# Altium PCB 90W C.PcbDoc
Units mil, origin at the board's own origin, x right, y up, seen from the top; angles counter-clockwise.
Board outline 3425 x 3275 mil, 2 copper layers (Top Layer, Bottom Layer); 75 components, 57 nets, 187 pads, 17 vias.
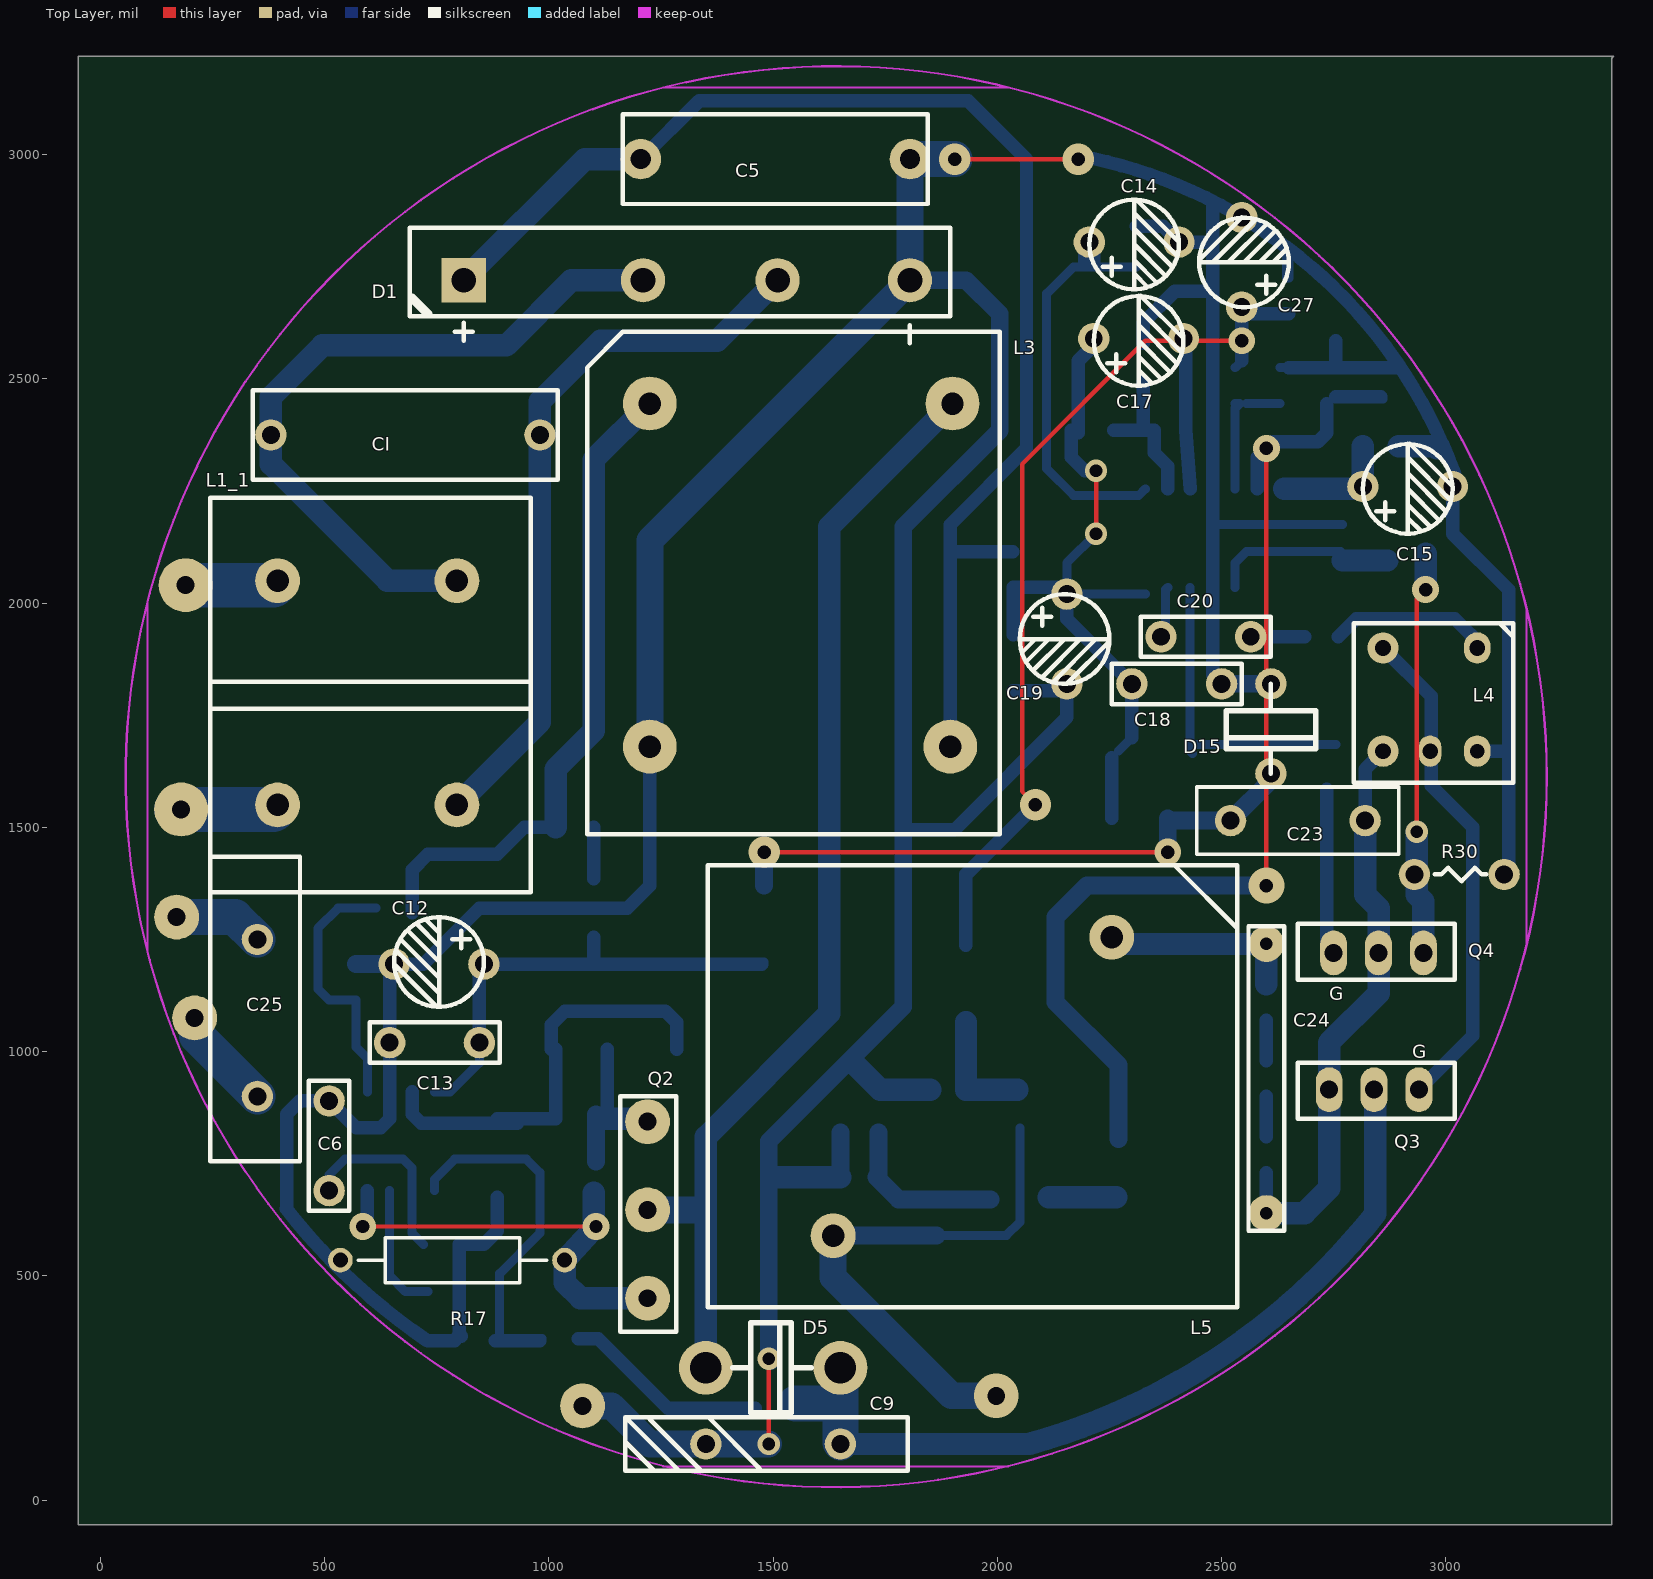
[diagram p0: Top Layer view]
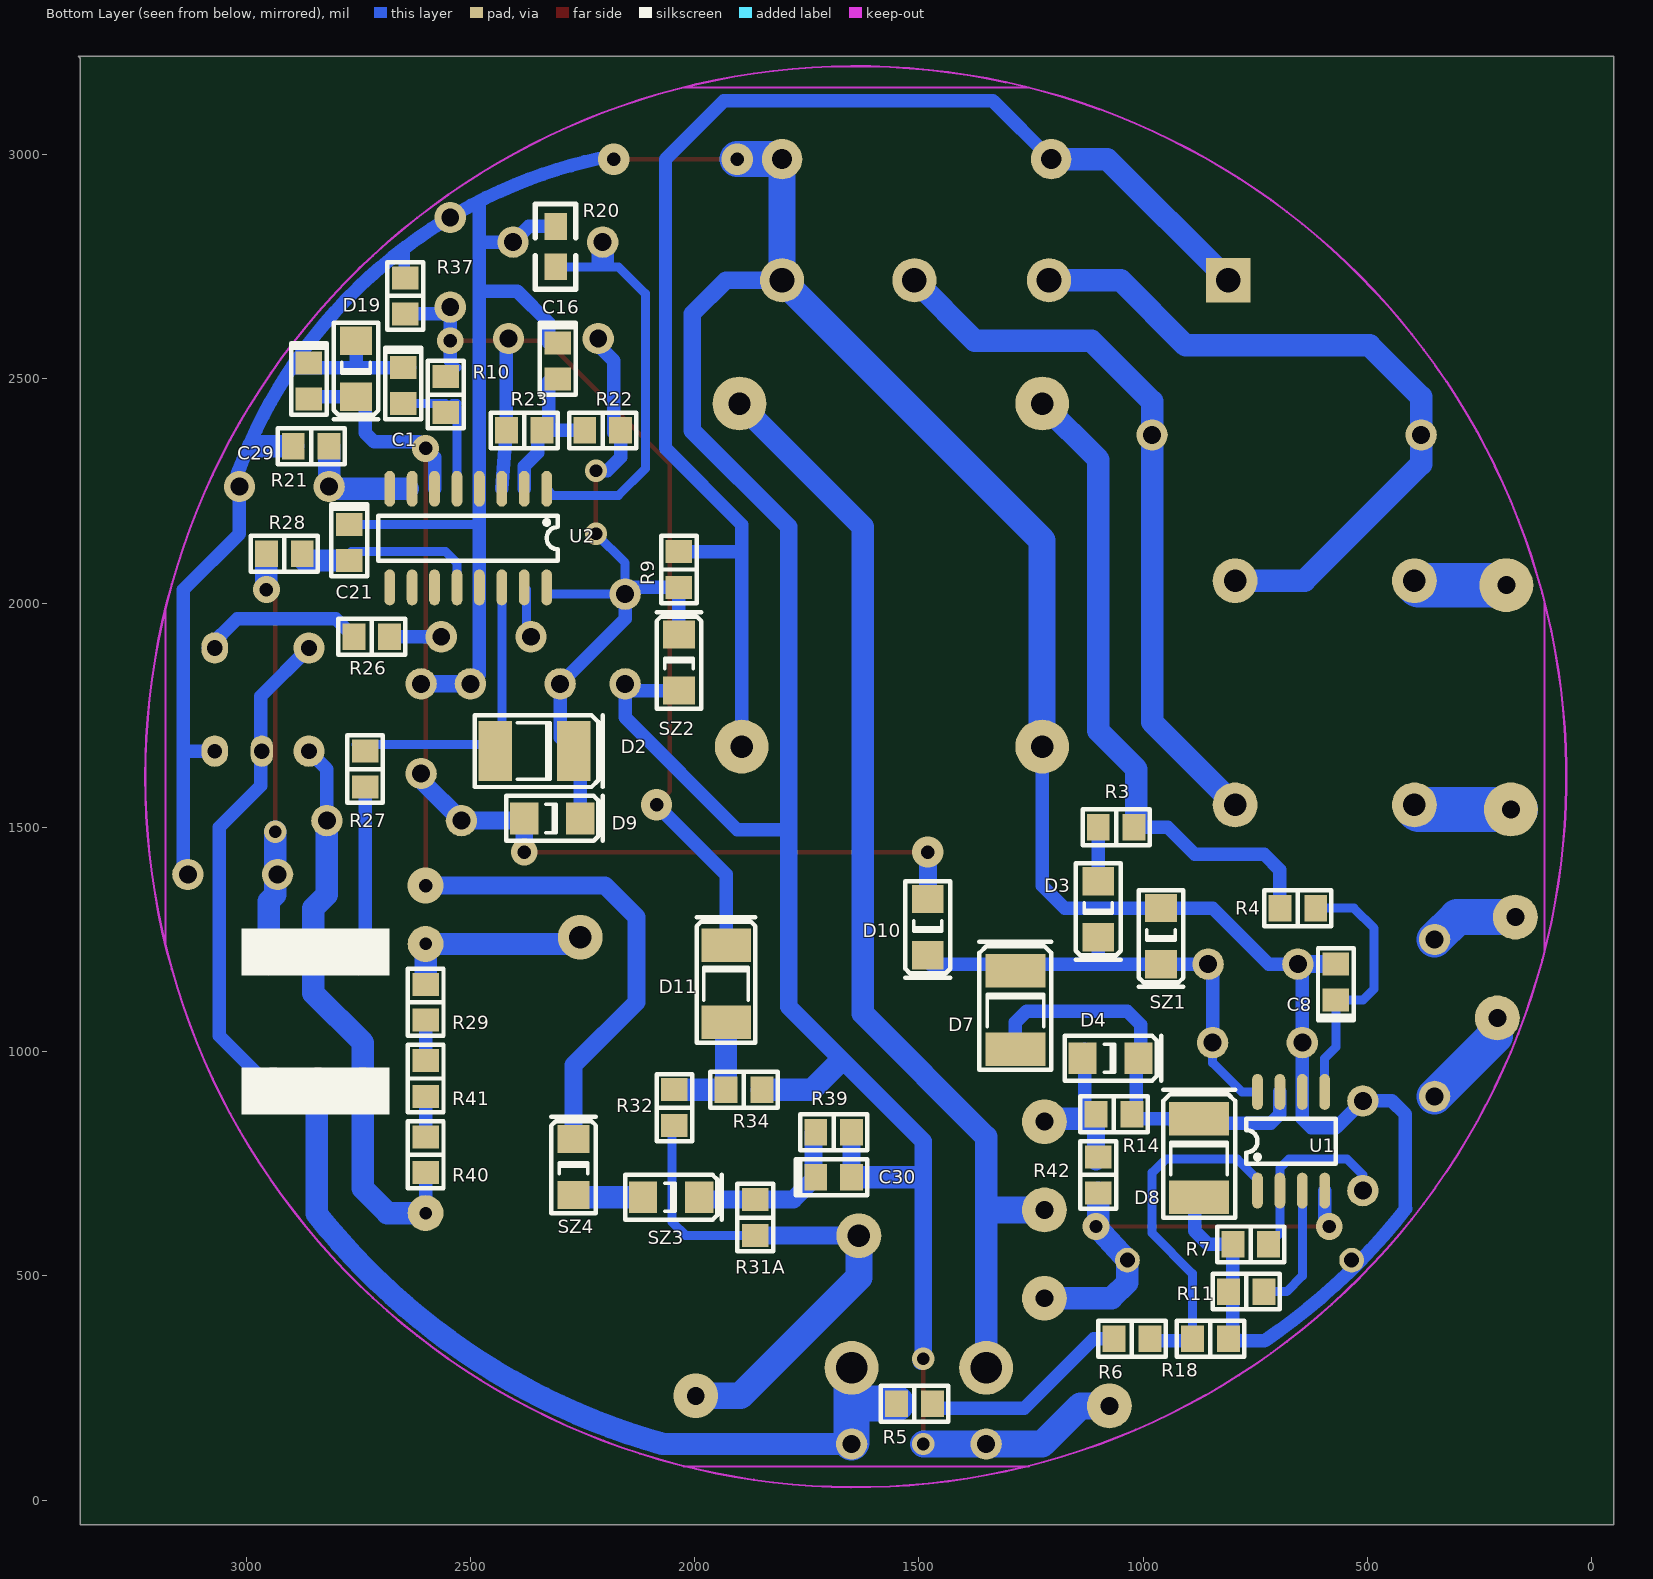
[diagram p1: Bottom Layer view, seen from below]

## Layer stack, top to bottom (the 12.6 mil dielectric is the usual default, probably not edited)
Top Layer: signal copper 1.4
Dielectric: dielectric 12.6, FR-4, Dk 4.8
Bottom Layer: signal copper 1.4

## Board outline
1685,3220 -50,3220 -50,-55 3370,-55 3370,3215 3375,3220

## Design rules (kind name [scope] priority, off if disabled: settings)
Clearance [All] p1: gap=10
HoleSize [All] p1: absolutevalues=TRUE maxlimit=150 minlimit=1 maxpercent=80.000 minpercent=20.000
PlaneClearance [All] p1: clearance=10
PolygonConnect [All] p1: connectstyle=Direct reliefconductorwidth=10 reliefentries=4 polygonreliefangle="90 Angle"
RoutingVias [All] p1: holewidth=28 width=50 viastyle="Through Hole" minholewidth=28 minwidth=50 maxholewidth=28 maxwidth=50
SolderMaskExpansion [All] p1: expansion=4
TestPointUsage [All] p1: valid=0 allowmultiple=FALSE
Testpoint [All] p1: side=15 testpointundercomponent=TRUE minsize=40 maxsize=100 preferedsize=60 minholesize=0 maxholesize=40 preferedholesize=32 testpointgrid=1 style=1023 order=0-112345678
Width [All] p1: maxlimit=100 minlimit=10 preferedwidth=10 toplayer_maxwidth=10 bottomlayer_minwidth=20 bottomlayer_prefwidth=40 minimp=50.000000 maximp=50.000000 favimp=50.000000
17 further rules are at their usual default settings.

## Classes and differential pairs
net class NewClass: GND

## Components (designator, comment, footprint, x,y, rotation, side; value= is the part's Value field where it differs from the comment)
C1 "Comment" C0805A 2650,2485 r270 bottom
C5 "CAP" RAD0.6B#1 1805,2990 r180 top
C6 "CAP" RAD0.2B 510,890 r270 top
C8 "CAP" C0805A 570,1155 r90 bottom
C9 "Cap2" RB.3/.6C 1650,125 r270 top
C12 "CAP" RB.2/.2 755,1195 r270 top
C13 "Comment" RAD0.2B 845,1020 r180 top
C14 "Cap" RB.2/.2 2305,2805 r90 top
C15 "Cap" RB.2/.2 2915,2260 r90 top
C16 "Cap" C0805A 2305,2540 r270 bottom
C17 "Cap2" RB.2/.2 2315,2590 r90 top
C18 "CAP" RAD0.2B 2500,1820 r180 top
C19 "Cap" RB.2/.2 2155,1920 r0 top
C20 "CAP" RAD0.2B 2565,1925 r180 top
C21 "CAP" C0805A 2770,2135 r270 bottom
C23 "CAP" RAD-0.3 2670,1515 r180 top
C24 "CAP" CAD0.6 2600,1240 r270 top
C25 "Comment" RAD0.6A 450,750 r90 top
C27 "Cap2" RB.2/.2 2545,2760 r180 top
C29 "Cap" C0805A 2860,2495 r270 bottom
C30 "Cap" C0805A 1690,720 r180 bottom
CI "" RAD0.6B#2 340,2275 r0 top
D1 "DIODEx4" HY_GBJ_606 810,2720 r90 top
D2 "Comment" CD4532-1812A 2350,1670 r180 bottom
D3 "DIODE" CD3216-1206A 1100,1320 r270 bottom
D4 "DIODE" CD3216-1206A 1075,985 r180 bottom
D5 "HIGH EFFICIENCY DIODES" DIODE0.7B 1350,295 r0 top
D7 "Comment" CD4532-1812A 1285,1100 r90 bottom
D8 "Comment" CD4532-1812A 875,770 r90 bottom
D9 "DIODE" CD3216-1206A 2320,1520 r180 bottom
D10 "DIODE" CD3216-1206A 1480,1280 r270 bottom
D11 "DIODE" CD4532-1810 1930,1160 r90 bottom
D15 "FFAST RECOVERY RECTIFIER" DIODE0.2A 2610,1820 r270 top
D19 "DIODE" CD3216-1206A 2755,2525 r270 bottom
L1_1 "Comment" EE2225_EMI 395,1550 r0 top
L3 "Comment" ER28 1090,2610 r270 top
L4 "INDUCTOR2:2" EE0808 2965,1670 r180 top
L5 "INDUCTOR2A" EI3028 2535,1415 r180 top
Q2 "K2628" MOS 1220,450 r90 top
Q3 "MOSFET-N" TO-220D 2840,915 r180 top
Q4 "MOSFET-N" TO-220D 2850,1220 r0 top
R3 "RES1" 2012[0805]A 1060,1500 r0 bottom
R4 "RES1" 2012[0805]A 655,1320 r180 bottom
R5 "RES1" 2012[0805]A 1510,215 r0 bottom
R6 "RES1" 2012[0805]A 1025,360 r180 bottom
R7 "Res1" 2012[0805]A 760,570 r180 bottom
R9 "RES1" 2012[0805]A 2035,2075 r90 bottom
R10 "RES1" 2012[0805]A 2555,2465 r270 bottom
R11 "RES1" 2012[0805]A 770,465 r0 bottom
R14 "RES1" 2012[0805]A 1065,860 r0 bottom
R17 "RES1" AXIAL-0.5 785,535 r0 top
R18 "RES1" 2012[0805]A 850,360 r0 bottom
R20 "RES1" 0805 2310,2840 r270 bottom
R21 "RES1" 2012[0805]A 2855,2350 r180 bottom
R22 "RES1" 2012[0805]A 2205,2385 r180 bottom
R23 "RES1" 2012[0805]A 2380,2385 r0 bottom
R26 "RES1" 2012[0805]A 2720,1925 r180 bottom
R27 "RES1" 2012[0805]A 2735,1630 r270 bottom
R28 "RES1" 2012[0805]A 2915,2110 r180 bottom
R29 "Res1" 2012[0805]A 2600,1110 r270 bottom
R30 "RES1" Axial0.2 3130,1395 r180 top
R31A "RES1" 2012[0805]A 1865,630 r270 bottom (schematic designator R31)
R32 "RES1" 2012[0805]A 2045,875 r90 bottom
R34 "RES1" 2012[0805]A 1890,915 r0 bottom
R37 "RES1" 2012[0805]A 2645,2685 r270 bottom
R39 "RES1" 2012[0805]A 1690,820 r0 bottom
R40 "Res1" 2012[0805]A 2600,770 r90 bottom
R41 "Res1" 2012[0805]A 2600,940 r270 bottom
R42 "RES1" 2012[0805]A 1100,725 r270 bottom
SZ1 "Zener" CD3216-1206A 960,1260 r270 bottom
SZ2 "Zener" CD3216-1206A 2035,1865 r90 bottom
SZ3 "Zener" CD3216-1206A 2055,675 r180 bottom
SZ4 "Zener" CD3216-1206A 2270,740 r90 bottom
U1 "IC" SO-8 745,690 r90 bottom
U2 "IC" "SO-16 A" 2330,2255 r270 bottom

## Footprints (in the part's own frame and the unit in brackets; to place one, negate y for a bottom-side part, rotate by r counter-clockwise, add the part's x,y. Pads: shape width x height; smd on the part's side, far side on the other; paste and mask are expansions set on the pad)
0805 [mil]
  rect 60x50 smd: 1(0,0) 2(90,0)
  silkscreen extent -50,-45 140,45
2012[0805]A [mm] "Chip Resistor; Body 2.0 x 1.3 mm (LxW typ)"
  rect 1.3x1.5 smd: 1(-1.016,0) 2(1.016,0)
  silkscreen extent -1.91,-1.02 1.91,1.02
Axial0.2 [mil]
  round 70 hole 40: 1(0,0) 2(200,0)
  silkscreen extent 40,-15 155,15
AXIAL-0.5 [mm] "Semiconductor Resistor; 2 Leads"
  round 1.4 hole 0.85: 1(-6.35,0) 2(6.35,0)
  silkscreen extent -5.33,-1.27 5.33,1.27
C0805A [mm] "Chip Capacitor; Body 2.0 x 1.2 mm (LxW typ)"
  rect 1.3x1.5 smd: 1(-1.016,0) 2(1.016,0)
  silkscreen extent -2.16,-1.02 1.91,1.02
CAD0.6 [mil]
  round 80 hole 28: 1(0,0) 2(600,0)
  silkscreen extent -40,-40 640,40
CD3216-1206A [mm] "Chip Diode; Body 3.2 x 1.6 mm (LxW typ)"
  rect 1.6x1.8 smd: 1(-1.524,0) 2(1.651,0)
  silkscreen extent -2.54,-1.27 2.92,1.27
CD4532-1810 [mm] "Chip Diode; Body 4.5 x 3.2 mm (LxW typ)"
  rect 1.9x2.8 smd: 1(-2.413,0) 2(1.95,0)
  silkscreen extent -3.56,-1.65 3.56,1.65
CD4532-1812A [mm] "Chip Diode; Body 4.5 x 3.2 mm (LxW typ)"
  rect 1.9x3.4 smd: 1(-2.413,0) 2(2.032,0)
  silkscreen extent -3.56,-2.03 3.68,2.03
DIODE0.2A [mil] "Tunnel Diode - Dependent Source Model; 2 Leads"
  round 70 hole 40: 1(0,0) 2(200,0)
  silkscreen extent 0,-100 200,100
DIODE0.7B [mil]
  round 120 hole 70: 1(0,0) 2(300,0)
  silkscreen extent 60,-100 235,100
EE0808 [mil]
  oval 59.06x70 hole 35: 1(-105,-230)
  round 70 hole 35: 3(105,-230) 4(105,0)
  oval 50x70 hole 35: 5(0,0)
  oval 59.06x70 hole 32: 6(-105,0)
  silkscreen extent -185,-285 170,70
EE2225_EMI [mil]
  round 100 hole 50: 1(0,0) 2(400,0) 3(400,500) 4(0,500)
  silkscreen extent -150,-195 565,685
EI3028 [mil]
  round 100 hole 50: 1(280,160) 5(901.1,825.51)
  silkscreen extent 0,0 1181,986
ER28 [mil]
  round 120 hole 50: 1(165,135) 5(930,135) 6(930,805) 10(165,810)
  silkscreen extent 5,-5 1125,915
HY_GBJ_606 [mm]
  rect 2.5x2.5 hole 1.4: 1(0,0)
  round 2.5 hole 1.4: 2(0,-10.16) 3(0,-17.78) 4(0,-25.273)
  silkscreen extent -3.56,-27.56 2.97,3.05
MOS [mil]
  round 100 hole 40: 1(0,0) 2(196.85,0) 3(393.7,0)
  silkscreen extent -75,-64 450,61
RAD0.2B [mil]
  round 70 hole 40: 1(0,0) 2(200,0)
  silkscreen extent -45,-45 245,45
RAD0.6A [mil]
  round 70 hole 40: 1(150,100) 2(500,100)
  silkscreen extent 5,5 685,205
RAD0.6B#1 [mil]
  round 90 hole 45: 1(0,0) 2(600,0)
  silkscreen extent -40,-100 640,100
RAD0.6B#2 [mil]
  round 70 hole 40: 1(40,100) 2(640,100)
  silkscreen extent 0,0 680,200
RAD-0.3 [mil] "Capacitor; 2 Leads"
  round 70 hole 40: 1(-150,0) 2(150,0)
  silkscreen extent -225,-75 225,75
RB.2/.2 [mil]
  round 70 hole 40: 1(0,100) 2(0,-100)
  silkscreen extent -105,-100 95,100
RB.3/.6C [mil]
  round 70 hole 40: 1(0,0) 2(0,-300)
  silkscreen extent -60,-480 60,150
SO-8 [mil]
  oval 80x24 smd: 1(0,0) 2(0,-50) 3(0,-100) 4(0,-150) 5(220,-150) 6(220,-100) 7(220,-50) 8(220,0)
  silkscreen extent 60,-175 160,25
"SO-16 A" [mil]
  oval 80x24 smd: 0(0,-350) 0(220,-350) 1(0,0) 2(0,-50) 3(0,-100) 4(0,-150) 5(0,-200) 6(0,-250) 7(0,-300) 8(220,-300) 9(220,-250) 10(220,-200) 11(220,-150) 12(220,-100) 13(220,-50) 14(220,0)
  silkscreen extent 60,-375 160,25
TO-220D [mil]
  oval 60x100 hole 40: 1(0,0) 2(-100,0) 3(100,0)
  silkscreen extent -180,-60 170,65

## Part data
C5 C23 C24: "POLYPROPYLENE FILM Capacitor"
C6 C8 C16 C18 C20 C21 C29 C30: "Ceramic Capacitor"
C9 C17 C27: "Electrolytic Capacitor"
C12 C14 C15 C19: library part Cap2, "Electrolytic Capacitor"
D3 D4 D9 D10 D11 D19: "Diode  75V,1A"
D5: library part DIODE, "Diode HIGH EFFICIENCY RECTIFIERS 600V, 3A"
D15: library part DIODE, "Diode FAST RECOVERY RECTIFIER 700V,1A"
L4: "EE08 Inductor"
L5: "EE25 Inductor"
Q3 Q4: "Transistor, MOSFET  600V, 6A"
R3 R4 R5 R6 R9 R10 R11 R14 R18 R20 R21 R22 R23 R26 R27 R28 R29 R31A R32 R34 R37 R39 R40 R41 R42: "Resistor 1/4W"
R7: "Resistor"
R17 R30: "Resistor 1W"
SZ1 SZ2: library part "D Zener", "Zener Diode 1W"
SZ3 SZ4: library part "D Zener", "Zener Diode 1/4W"
U1: library part 59039, "IC, Power Factor Controller"
U2: library part M8145, "IC, Ballast Driver"

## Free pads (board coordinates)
  round 100 hole 40: 0(170,1300) 0(1075,210) 1(210,1075)
  round 120 hole 40: 0(190,2040) 1(180,1540)

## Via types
v1: diameter 60, hole 30, Top Layer to Bottom Layer, 6 vias
v2: diameter 50, hole 28, Top Layer to Bottom Layer, 5 vias
v3: diameter 70, hole 30, Top Layer to Bottom Layer, 4 vias
v4: diameter 100, hole 40, Top Layer to Bottom Layer, 1 vias
v5: diameter 80, hole 30, Top Layer to Bottom Layer, 1 vias

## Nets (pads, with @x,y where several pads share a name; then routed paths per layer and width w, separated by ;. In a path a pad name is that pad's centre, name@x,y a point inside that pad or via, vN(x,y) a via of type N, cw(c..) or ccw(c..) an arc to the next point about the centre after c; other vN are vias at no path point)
GND: C1.1 C5.1 C6.1 C8.2 C9.2 C12.2 C13.2 C14.2 C15.2 C16.1 C18.1 C19.2 C21.1 C27.2 C29.1 C30.2 D1.4 D8.1 D15.1 D19.1 L3.5 L4.6 pad.0@1075,210 R7.1 R11.2 R17.1 R18.1 R20.1 R21.1 R30.1 R34.1 R37.1 R39.1 SZ1.1 SZ2.1 U1.6 U2.4 U2.11 | length 13879.7
  Top Layer w10: v2(1490,125) v2(1490,315) ; v3(1905,2990) v3(2180,2990)
  Bottom Layer w20: 2475,2895 2480,2890 ; 2485,2175 C21.1 ; C27.2@2530,2845 2530,2869.44 C27.2@2530,2875 ; C1.1@2630,2525 C1.1 ; R37.1 2645,2793.52 2645,2795 ; R37.1@2650,2725 2650,2785 ; 2895,2525 2900,2520 ; 2980,2345 2995,2345
  Bottom Layer w30: 414.43,649.56 ccw(c1507.5,1502.5) 727.46,356.27 ; 415,654.8 415,860 445,890 C6.1 570,830 625,830 645,850 U1.6 C13.2 645,1190 C12.2@650,1195 ; C12.2 720,1195 845,1320 SZ1.1 1175,1320 1225,1370 L3.5 L3.5@1225,1640 ; 730,355 790,355 R18.1@800,370 ; R18.1@805,365 R18.1@800,370 ; D8.1@885,675 885,600 855,570 R7.1 R18.1@800,370 ; 1790,1495 1905,1495 2155,1745 C19.2 ; SZ2.1 C19.2@2140,1805 ; v3@2181.48,2997.91 cw(c1977.48,1907.48) 2400,2933.21 cw(c1977.48,1907.48) 2530,2869.44 cw(c1977.48,1907.48) 2645,2793.52 cw(c1977.48,1907.48) C15.2@3030.89,2255.29 ; R20.1 2370,2840 C14.2 2475,2805 2480,2800 ; C16.1@2325,2580 2325,2625 2395,2695 2480,2695 ; 2480,2890 2480,2800 ; C18.1 2480,1840 U2.11 U2.4 2480,2695 ; C1.1 2895,2525 ; 2755,2530 D19.1 ; C15.2 3015,2155 3140,2030 3140,1670 ; L4.6 3140,1670 ; R30.1@3140,1395 3140,1670 ; 2480,2695 2480,2800
  Bottom Layer w39.37: v2@1495,310 v2(1490,315) 1490,800 1790,1100 1790,2170 2005,2385 2005,2645 1930,2720 D1.4 ; C18.1 D15.1
  Bottom Layer w40: C8.2 C12.2@650,1195 ; C30.2 R39.1
  Bottom Layer w50: 1505,720 C30.2 ; 1679.29,974.29 1738.57,915 R34.1 ; R21.1 2975,2350 2980,2345
  Bottom Layer w60: pad.0@1075,210 1140,210 1225,125 C9.2 v2(1490,125) ; L3.5 1225,2140 D1.4 C5.1
  Bottom Layer w80: C5.1 v3(1905,2990)
L: 
N: 
NetC2_2: 
NetC4_1: 
NetC5_2: C5.2 D1.1 L3.6 R9.2 | length 2994.6
  Bottom Layer w30: C5.2 1334.8,3119.8 1935.2,3119.8 2065,2990 2065,2345 1895,2175 1895,2154.8 L3.6 ; 1895,2115 R9.2@2034.8,2115
  Bottom Layer w50: D1.1 1080,2990 C5.2
NetC6_2: C6.2 R7.2 U1.2 | length 423.1
  Bottom Layer w20: C6.2 510,725 545,760 675,760 695,740 U1.2 695,595 R7.2
NetC8_1: C8.1 R4.2 U1.5 | length 594.4
  Bottom Layer w20: U1.5 595,985 570,1010 C8.1 510,1115 485,1140 485,1275 530,1320 R4.2
NetC9_1: C9.1 D5.2 Q3.1 R5.2 | length 1911.4
  Bottom Layer w30: Q3.1 Q3.1@2842.49,912.51
  Bottom Layer w50: C9.1 2070.5,125 ccw(c1670,1565) 2842.49,638.03 ; 2842.49,638.03 Q3.1@2842.49,912.51
  Bottom Layer w60: 1639.8,215 1650,204.8
  Bottom Layer w80: R5.2 1639.8,215 ; C9.1@1650,128.75 1650,204.8 D5.2
NetC11_2: 
NetC12_1: C12.1 C13.1 D3.2 D7.2 D10.2 SZ1.2 U1.8 | length 1038.1
  Bottom Layer w20: U1.8 780,910 845,975 C13.1 ; C12.1@845,1185 C12.1 ; D10.2@1475,1195 D10.2@1480,1200
  Bottom Layer w30: C13.1 C12.1@845,1185 ; C12.1 SZ1.2 1100,1195 ; D3.2 1100,1195 ; D10.2@1475,1195 1100,1195
NetC14_1: C14.1 R20.2 U2.1 | length 913
  Bottom Layer w20: 2205,2755 2200,2750 ; R20.2 2200,2750 ; U2.1 2315,2240 2170,2240 2110,2300 2110,2690 2170,2750 2200,2750
  Bottom Layer w50: 2205,2765 C14.1
NetC15_1: C15.1 R21.2 U2.0@2680,2255 U2.7 | length 270
  Bottom Layer w50: U2.7@2640,2255 2680,2255 2815,2255 R21.2
NetC16_2: C16.2 R22.1 R23.1 U2.2 | length 344.5
  Bottom Layer w30: R22.1@2260,2385 R23.1@2330,2385 ; C16.2@2325,2495 2325,2390 R23.1@2330,2385 ; U2.2 2380,2305 2350,2335 2350,2385 R23.1@2330,2385
NetC17_2: C17.2 R23.2 U2.3 | length 335.4
  Bottom Layer w30: C17.2@2420,2590 R23.2 U2.3
NetC20_1: C20.1 R26.2 | length 120
  Bottom Layer w30: C20.1 R26.2@2685,1925
NetC20_2: C20.2 U2.13 | length 112.1
  Bottom Layer w20: C20.2@2375,1925 2375,2030 U2.13
NetC21_2: C21.2 R28.2 U2.10 | length 407.4
  Bottom Layer w20: U2.10 2530,2090 2555,2115 2765,2115 C21.2@2770,2110
  Bottom Layer w50: C21.2 R28.2@2870,2095
NetC23_1: C23.1 C24.2 L4.4 Q3.3 Q4.1 R40.1 | length 1302.3
  Bottom Layer w30: C24.2 R40.1 ; C23.1 2820,1630 L4.4
  Bottom Layer w50: C24.2 2685,640 2740,695 Q3.3 2740,1020 2850,1130 Q4.1 2850,1320 2820,1350 C23.1
NetC23_2: C23.2 D9.1 D10.1 D15.2 | length 1334.4
  Top Layer w10: v3(1480,1445) v1(2380,1445)
  Bottom Layer w40: D10.1@1480,1370 v3(1480,1445) ; v1(2380,1445) D9.1 2385,1515 C23.2 2610,1605 D15.2
NetC25_1: 
NetC25_2: 
NetC26_1: 
NetC26_2: 
NetC27_1: C27.1 D11.2 R10.1 R37.2 | length 1985
  Top Layer w10: v3(2085,1550) 2055,1580 2055,2310 2330,2585 v1(2545,2585)
  Bottom Layer w20: R10.1@2530,2525 2545,2540
  Bottom Layer w30: D11.2 1930,1395 v3(2085,1550) ; 2545,2540 2545,2645 R37.2@2650,2645
NetC28_1: 
NetC30_1: C30.1 R31A.1 R39.2 SZ3.2 | length 382.8
  Bottom Layer w20: SZ3.2@1985,670 SZ3.2
  Bottom Layer w40: C30.1 1780,670 R31A.1 SZ3.2@1985,670 ; C30.1@1735,720 R39.2@1735,820
NetCNR1_1: CI.1 D1.2 L1_1.3 | length 1610.4
  Bottom Layer w50: L1_1.3 640,2050 380,2310 CI.1 380,2460 495,2575 905,2575 1050,2720 D1.2
NetCNR1_2: 
NetD3_1: D3.1 R3.2 | length 115
  Bottom Layer w30: D3.1@1100,1385 R3.2
NetD4_1: D4.1 Q2.3 R14.2 R42.1 | length 379.7
  Bottom Layer w30: R14.2@1105,840 R14.2@1110,835 ; R14.2@1130,850 D4.1@1130,1005 ; Q2.3@1213.7,850 Q2.3
  Bottom Layer w40: R42.1@1105,755 1105,840 R14.2
  Bottom Layer w50: R14.2@1110,850 Q2.3@1213.7,850
NetD4_2: D4.2 D7.1 D8.2 R14.1 U1.7 | length 1003.1
  Bottom Layer w30: U1.7 695,860 715,840 D8.2@930,840 ; D8.2@885,850 1015,850 1015,1005 D4.2@1010,1010 ; D4.2@1005,1005 1005,1060 1035,1090 1260,1090 1285,1065 D7.1
NetD5_1: D5.1 L3.10 Q2.2 | length 2491
  Bottom Layer w50: D5.1 1350,640 ; 1350,646.85 1350,810 1625,1085 1625,2170 L3.10
  Bottom Layer w60: Q2.2 1340,646.85
NetD11_1: D11.1 R32.2 R34.2 | length 265
  Bottom Layer w50: D11.1 R34.2 R32.2
NetD16_1: 
NetD18_1: 
NetF1_2: CI.2 D1.3 L1_1.2 | length 1618.5
  Bottom Layer w50: L1_1.2 980,1735 CI.2 980,2450 1115,2585 1375,2585 D1.3
NetL3_8: L3.1 R3.1 R4.1 | length 1486.3
  Bottom Layer w30: R4.1@695,1310 R4.1 695,1405 730,1440 885,1440 945,1500 R3.1@1015,1500
  Bottom Layer w50: R3.1@1015,1500 1015,1630 1100,1715 1100,2320 L3.1
NetL4_1: L4.1 R26.1 | length 368.5
  Bottom Layer w30: R26.1 2800,1965 3020,1965 L4.1@3085,1900
NetL4_3: L4.3 Q3.2 | length 1117.5
  Bottom Layer w30: L4.3 2967.5,1792.5 2967.5,1592.5 3060,1500 3060,1035 Q3.2
NetL5_5: L5.5 R31A.2 R32.1 | length 1198.3
  Bottom Layer w20: R31A.2 2020,590 2050,620 R32.1@2050,830
  Bottom Layer w30: R31A.2@1864.49,589.49 R31A.2
  Bottom Layer w40: L5.5@1640.51,589.49 R31A.2@1864.49,589.49
  Bottom Layer w60: L5.5 1633.9,496.1 1897.5,232.5 v4(1997.5,232.5)
NetL6_5: 
NetQ1_3: Q2.1 R17.2 R42.2 U1.4 | length 1131.8
  Top Layer w10: v1(585,610) v1(1105,610)
  Bottom Layer w20: R17.2 v1(1105,610)
  Bottom Layer w30: v1@595,610 U1.4 ; v1@1100,615 v1(1105,610)
  Bottom Layer w50: v1@1100,615 R42.2 ; v1(1105,610) R17.2 1035,485 1070,450 Q2.1
NetQ4_2: Q4.2 R27.2 | length 365
  Bottom Layer w30: Q4.2@2735,1220 R27.2@2735,1585
NetQ4_3: Q4.3 R28.1 R30.2 | length 915.7
  Top Layer w10: v2(2935,1490) 2935,2010 v1(2955,2030)
  Bottom Layer w20: R30.2@2935,1415 R30.2@2950,1400
  Bottom Layer w50: v2(2935,1490) 2935,1350 2950,1335 Q4.3 ; v1@2955,2040 R28.1
NetR2_2: R11.1 U1.3 | length 319.5
  Bottom Layer w20: U1.3@645,660 U1.3 645,500 680,465 R11.1
NetR5_1: R5.1 R6.1 | length 459.2
  Bottom Layer w30: R6.1 1110,360 1265,205 R5.1@1460,205
NetR6_1: R6.2 R18.2 U1.1 | length 805.4
  Bottom Layer w20: U1.1 745,715 790,760 950,760 980,730 980,595 890,505 R18.2 ; R6.2@980,355 R6.2
  Bottom Layer w30: R18.2@880,355 R6.2@980,355
NetR10_2: C1.2 R10.2 U2.5 | length 279.1
  Bottom Layer w20: U2.5 2530,2435 2540,2445 R10.2@2530,2445 ; R10.2@2555,2445 C1.2@2630,2445
NetR24_1: 
NetR27_1: D2.1 R27.1 U2.12 | length 682.1
  Bottom Layer w20: U2.12 2430,1670 D2.1@2435,1665 ; D2.1@2445,1685 R27.1@2755,1685
NetR29_2: R29.2 R41.1 | length 90
  Bottom Layer w30: R41.1 R29.2
NetR40_2: R40.2 R41.2 | length 90
  Bottom Layer w30: R40.2 R41.2
NetSZ3_1: SZ3.1 SZ4.1 | length 157.1
  Bottom Layer w30: SZ4.1@2265,675 SZ4.1
  Bottom Layer w50: SZ3.1 SZ4.1@2265,675
SD3A: C24.1 L5.1 R29.1 | length 441.2
  Bottom Layer w50: L5.1 2270,1240 2435,1240 C24.1 R29.1
SD3B: C29.2 D19.2 SZ4.2 U2.6 | length 2446.8
  Top Layer w10: v5(2600,1370) v1(2600,2345)
  Bottom Layer w20: C29.2@2855,2460 C29.2
  Bottom Layer w30: U2.6 2580,2325 2615,2360 2715,2360 2735,2380 D19.2@2735,2445 ; D19.2 C29.2@2855,2460
  Bottom Layer w40: SZ4.2 2270,970 2130,1110 2130,1300 2200,1370 v5(2600,1370)
VCC: C17.1 C18.2 C19.1 D2.2 D9.2 R9.1 R22.2 SZ2.2 U2.14 | length 1652
  Top Layer w10: v2(2220,2155) v2(2220,2295)
  Bottom Layer w20: C19.1@2140,2035 C19.1 ; v2(2220,2155) 2155,2090 C19.1 ; D2.2 D2.2@2300,1700 ; U2.14@2330,2020 C19.1
  Bottom Layer w30: SZ2.2 R9.1 C19.1@2140,2035 ; C19.1 2155,1965 C18.2 ; R22.2 2165,2325 2195,2295 v2(2220,2295) ; R22.2@2180,2380 2180,2540 C17.1@2230,2590 ; D9.2 D2.2@2255,1655 ; C18.2@2280,1840 C18.2 ; D2.2@2300,1700 C18.2
pads on no net: C25.1 C25.2 L1_1.1 L1_1.4 L4.5 U2.0@2680,2035 U2.8 U2.9
copper on no net: | length 872
  Bottom Layer w50: 170,1300 175,1305
  Bottom Layer w80: 170,1300 300,1300 350,1250 ; 215,1070 215,1035 350,900 ; 385,1540 395,1550 ; 385,2040 395,2050
  Bottom Layer w100: 170,1540 385,1540 ; 190,2040 385,2040

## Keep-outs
Keep-Out Layer:
  circle w5: c1640.6,1613 r1584.4
  lines w5: 105,1225 105,2005 ; 1255,75 2025,75 ; 1255,3150 2025,3150 ; 3180,1235 3180,1990

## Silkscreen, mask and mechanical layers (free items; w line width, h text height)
Top Overlay:
  text "G" at 2740,1115 h30
  text "G" at 2925,985 h30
